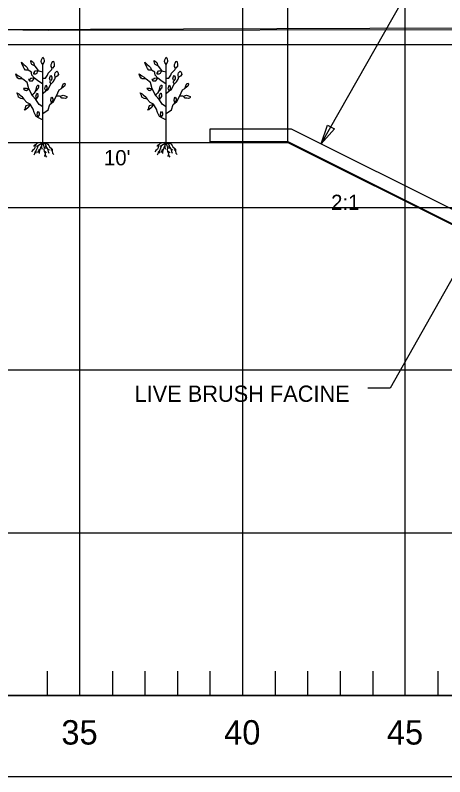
# Model space of a CAD drawing. Extents: x 1578769 to 1579225, y 724002 to 724828.
# Drawn here: x 1578858.15 to 1578871.35, y 724249.64 to 724273.06 of the extents above; entities that cross this region are included whole.
import ezdxf

# ---------------------------------------------------------------- set-up
doc = ezdxf.new("R2010")
doc.units = 0
for name, color, linetype in [('1', 7, 'Continuous'), ('Default', 7, 'Continuous'), ('Old_Level_1', 7, 'Continuous'), ('Old_Level_41', 7, 'Continuous'), ('Old_Level_42', 7, 'Continuous'), ('R_Exist Surface', 7, 'Continuous'), ('R_Fin Surface', 7, 'Continuous')]:
    doc.layers.add(name, color=color, linetype=linetype)

msp = doc.modelspace()

# ---------------------------------------------------------------- linework, layer by layer
at = {"layer": '1'}
for p, q in [((1578866.531, 724269.141), (1578866.531, 724276.038)), ((1578859, 724269.141), (1578859, 724271.541)), ((1578862.79, 724269.141), (1578862.79, 724271.541)), ((1578859.005, 724269.136), (1578859.006, 724269.14)), ((1578862.794, 724269.136), (1578862.796, 724269.14))]:
    msp.add_line(p, q, dxfattribs=at)
for points in [[(1578867.555, 724269.098), (1578873.081, 724278.846), (1578873.766, 724278.846)], [(1578859.287, 724271.427), (1578859.256, 724271.484), (1578859.256, 724271.541), (1578859.275, 724271.585), (1578859.3, 724271.636), (1578859.325, 724271.642), (1578859.35, 724271.56), (1578859.35, 724271.522), (1578859.344, 724271.49), (1578859.293, 724271.427)], [(1578863.077, 724271.427), (1578863.045, 724271.484), (1578863.045, 724271.541), (1578863.064, 724271.585), (1578863.09, 724271.636), (1578863.115, 724271.642), (1578863.14, 724271.56), (1578863.14, 724271.522), (1578863.134, 724271.49), (1578863.083, 724271.427)], [(1578858.987, 724270.947), (1578858.937, 724270.973), (1578858.836, 724271.048), (1578858.748, 724271.124), (1578858.659, 724271.213), (1578858.647, 724271.288), (1578858.647, 724271.301), (1578858.546, 724271.364)], [(1578859, 724271.301), (1578858.912, 724271.326), (1578858.861, 724271.351), (1578858.836, 724271.402), (1578858.76, 724271.49), (1578858.748, 724271.503)], [(1578859, 724271.124), (1578859.076, 724271.124), (1578859.139, 724271.213), (1578859.164, 724271.276), (1578859.278, 724271.389), (1578859.29, 724271.427)], [(1578859.379, 724271.124), (1578859.366, 724271.244), (1578859.379, 724271.288), (1578859.429, 724271.339), (1578859.461, 724271.307), (1578859.48, 724271.238), (1578859.435, 724271.187), (1578859.379, 724271.137)], [(1578862.777, 724270.947), (1578862.727, 724270.973), (1578862.626, 724271.048), (1578862.537, 724271.124), (1578862.449, 724271.213), (1578862.436, 724271.288), (1578862.436, 724271.301), (1578862.335, 724271.364)], [(1578862.79, 724271.301), (1578862.701, 724271.326), (1578862.651, 724271.351), (1578862.626, 724271.402), (1578862.55, 724271.49), (1578862.537, 724271.503)], [(1578862.79, 724271.124), (1578862.866, 724271.124), (1578862.929, 724271.213), (1578862.954, 724271.276), (1578863.068, 724271.389), (1578863.08, 724271.427)], [(1578863.168, 724271.124), (1578863.156, 724271.244), (1578863.169, 724271.288), (1578863.219, 724271.339), (1578863.251, 724271.307), (1578863.27, 724271.238), (1578863.225, 724271.187), (1578863.169, 724271.137)], [(1578858.381, 724271.086), (1578858.337, 724271.099), (1578858.262, 724271.105), (1578858.23, 724271.124), (1578858.192, 724271.181), (1578858.167, 724271.244), (1578858.167, 724271.25), (1578858.205, 724271.219), (1578858.255, 724271.194), (1578858.325, 724271.149), (1578858.381, 724271.086)], [(1578859, 724270.24), (1578858.886, 724270.316), (1578858.785, 724270.467), (1578858.684, 724270.581), (1578858.571, 724270.796), (1578858.52, 724270.985), (1578858.381, 724271.086)], [(1578859, 724270.657), (1578859.013, 724270.657), (1578859.088, 724270.733), (1578859.151, 724270.758), (1578859.24, 724270.935), (1578859.316, 724271.01), (1578859.366, 724271.086), (1578859.379, 724271.124)], [(1578859.233, 724271.036), (1578859.208, 724271.099), (1578859.221, 724271.175), (1578859.24, 724271.206), (1578859.271, 724271.156), (1578859.271, 724271.099), (1578859.233, 724271.036)], [(1578862.171, 724271.086), (1578862.127, 724271.099), (1578862.051, 724271.105), (1578862.02, 724271.124), (1578861.982, 724271.181), (1578861.957, 724271.244), (1578861.957, 724271.25), (1578861.995, 724271.219), (1578862.045, 724271.194), (1578862.115, 724271.149), (1578862.171, 724271.086)], [(1578862.79, 724270.24), (1578862.676, 724270.316), (1578862.575, 724270.467), (1578862.474, 724270.581), (1578862.361, 724270.796), (1578862.31, 724270.985), (1578862.171, 724271.086)], [(1578862.79, 724270.657), (1578862.802, 724270.657), (1578862.878, 724270.733), (1578862.941, 724270.758), (1578863.03, 724270.935), (1578863.105, 724271.01), (1578863.156, 724271.086), (1578863.168, 724271.124)], [(1578863.023, 724271.036), (1578862.998, 724271.099), (1578863.011, 724271.175), (1578863.03, 724271.206), (1578863.061, 724271.156), (1578863.061, 724271.099), (1578863.023, 724271.036)], [(1578859.088, 724270.733), (1578859.063, 724270.796), (1578859.076, 724270.871), (1578859.095, 724270.903), (1578859.126, 724270.853), (1578859.126, 724270.796), (1578859.088, 724270.733)], [(1578859.24, 724270.935), (1578859.233, 724270.973), (1578859.215, 724270.998), (1578859.233, 724271.036)], [(1578859.568, 724270.808), (1578859.6, 724270.89), (1578859.631, 724270.954), (1578859.675, 724270.966), (1578859.682, 724270.935), (1578859.663, 724270.878), (1578859.625, 724270.84), (1578859.568, 724270.808)], [(1578862.878, 724270.733), (1578862.853, 724270.796), (1578862.866, 724270.871), (1578862.884, 724270.903), (1578862.916, 724270.853), (1578862.916, 724270.796), (1578862.878, 724270.733)], [(1578863.03, 724270.935), (1578863.023, 724270.973), (1578863.004, 724270.998), (1578863.023, 724271.036)], [(1578863.358, 724270.808), (1578863.389, 724270.89), (1578863.421, 724270.954), (1578863.465, 724270.966), (1578863.471, 724270.935), (1578863.453, 724270.878), (1578863.415, 724270.84), (1578863.358, 724270.808)], [(1578858.571, 724270.796), (1578858.497, 724270.802), (1578858.439, 724270.802), (1578858.401, 724270.802), (1578858.42, 724270.783), (1578858.458, 724270.754), (1578858.497, 724270.744), (1578858.573, 724270.792)], [(1578858.684, 724270.581), (1578858.703, 724270.644), (1578858.754, 724270.682), (1578858.785, 724270.733)], [(1578859, 724270.032), (1578859.164, 724270.151), (1578859.215, 724270.316), (1578859.328, 724270.404), (1578859.416, 724270.581), (1578859.505, 724270.758), (1578859.568, 724270.808)], [(1578862.361, 724270.796), (1578862.286, 724270.802), (1578862.229, 724270.802), (1578862.191, 724270.802), (1578862.21, 724270.783), (1578862.248, 724270.754), (1578862.286, 724270.744), (1578862.363, 724270.792)], [(1578862.474, 724270.581), (1578862.493, 724270.644), (1578862.544, 724270.682), (1578862.575, 724270.733)], [(1578862.79, 724270.032), (1578862.954, 724270.151), (1578863.004, 724270.316), (1578863.118, 724270.404), (1578863.206, 724270.581), (1578863.295, 724270.758), (1578863.358, 724270.808)], [(1578859.003, 724269.837), (1578858.964, 724269.846), (1578858.888, 724269.894), (1578858.793, 724269.942), (1578858.735, 724270.066), (1578858.697, 724270.171), (1578858.611, 724270.324), (1578858.506, 724270.372), (1578858.411, 724270.477), (1578858.411, 724270.477)], [(1578859.269, 724270.367), (1578859.244, 724270.43), (1578859.257, 724270.506), (1578859.276, 724270.537), (1578859.307, 724270.487), (1578859.307, 724270.43), (1578859.269, 724270.367)], [(1578859.416, 724270.581), (1578859.48, 724270.581), (1578859.505, 724270.581), (1578859.536, 724270.568)], [(1578859.536, 724270.568), (1578859.625, 724270.6), (1578859.688, 724270.575), (1578859.732, 724270.556), (1578859.732, 724270.524), (1578859.713, 724270.505), (1578859.682, 724270.499), (1578859.637, 724270.505), (1578859.587, 724270.505), (1578859.536, 724270.568)], [(1578862.792, 724269.837), (1578862.754, 724269.846), (1578862.678, 724269.894), (1578862.582, 724269.942), (1578862.525, 724270.066), (1578862.487, 724270.171), (1578862.401, 724270.324), (1578862.296, 724270.372), (1578862.201, 724270.477), (1578862.201, 724270.477)], [(1578863.059, 724270.367), (1578863.034, 724270.43), (1578863.047, 724270.506), (1578863.065, 724270.537), (1578863.097, 724270.487), (1578863.097, 724270.43), (1578863.059, 724270.367)], [(1578863.206, 724270.581), (1578863.269, 724270.581), (1578863.295, 724270.581), (1578863.326, 724270.568)], [(1578863.326, 724270.568), (1578863.415, 724270.6), (1578863.478, 724270.575), (1578863.522, 724270.556), (1578863.522, 724270.524), (1578863.503, 724270.505), (1578863.471, 724270.499), (1578863.427, 724270.505), (1578863.377, 724270.505), (1578863.326, 724270.568)], [(1578858.849, 724269.927), (1578858.824, 724269.991), (1578858.837, 724270.066), (1578858.856, 724270.098), (1578858.887, 724270.047), (1578858.887, 724269.991), (1578858.849, 724269.927)], [(1578862.639, 724269.927), (1578862.614, 724269.991), (1578862.626, 724270.066), (1578862.645, 724270.098), (1578862.677, 724270.047), (1578862.677, 724269.991), (1578862.639, 724269.927)], [(1578859, 724269.141), (1578858.949, 724269.135), (1578858.933, 724269.139), (1578858.875, 724269.131), (1578858.84, 724269.124), (1578858.813, 724269.108), (1578858.782, 724269.077), (1578858.758, 724269.042), (1578858.751, 724269.007), (1578858.751, 724268.976), (1578858.735, 724268.941), (1578858.724, 724268.926), (1578858.685, 724268.898), (1578858.65, 724268.852)], [(1578858.782, 724269.077), (1578858.739, 724269.058), (1578858.724, 724269.034), (1578858.712, 724269.026)], [(1578859, 724269.141), (1578858.933, 724269.092), (1578858.894, 724269.073), (1578858.855, 724269.042), (1578858.836, 724269.003), (1578858.828, 724268.972), (1578858.789, 724268.887), (1578858.755, 724268.844), (1578858.743, 724268.794), (1578858.727, 724268.751)], [(1578858.855, 724269.042), (1578858.813, 724269.034), (1578858.809, 724269.019)], [(1578859, 724269.141), (1578858.96, 724269.046), (1578858.925, 724268.992), (1578858.914, 724268.941), (1578858.898, 724268.902), (1578858.887, 724268.844), (1578858.887, 724268.805)], [(1578858.96, 724269.046), (1578858.96, 724268.992), (1578858.964, 724268.968), (1578858.976, 724268.937)], [(1578859, 724269.141), (1578859.084, 724269.125), (1578859.127, 724269.112), (1578859.154, 724269.092), (1578859.181, 724269.054), (1578859.201, 724269.007), (1578859.267, 724268.96), (1578859.29, 724268.933), (1578859.29, 724268.875), (1578859.294, 724268.817), (1578859.333, 724268.778)], [(1578859, 724269.141), (1578859.069, 724269.104), (1578859.092, 724269.05), (1578859.104, 724268.995), (1578859.139, 724268.949), (1578859.162, 724268.863), (1578859.185, 724268.813)], [(1578859, 724269.141), (1578859.007, 724269.077), (1578859.018, 724269.05), (1578859.03, 724269.011), (1578859.038, 724268.995), (1578859.038, 724268.964), (1578859.026, 724268.926), (1578859.038, 724268.879), (1578859.053, 724268.844), (1578859.073, 724268.805), (1578859.073, 724268.77), (1578859.084, 724268.728), (1578859.108, 724268.693)], [(1578859.092, 724269.05), (1578859.08, 724269.019), (1578859.069, 724269.003), (1578859.088, 724268.957)], [(1578862.79, 724269.141), (1578862.738, 724269.135), (1578862.723, 724269.139), (1578862.665, 724269.131), (1578862.63, 724269.124), (1578862.603, 724269.108), (1578862.572, 724269.077), (1578862.548, 724269.042), (1578862.541, 724269.007), (1578862.541, 724268.976), (1578862.525, 724268.941), (1578862.513, 724268.926), (1578862.475, 724268.898), (1578862.44, 724268.852)], [(1578862.572, 724269.077), (1578862.529, 724269.058), (1578862.513, 724269.034), (1578862.502, 724269.026)], [(1578862.79, 724269.141), (1578862.723, 724269.092), (1578862.684, 724269.073), (1578862.645, 724269.042), (1578862.626, 724269.003), (1578862.618, 724268.972), (1578862.579, 724268.887), (1578862.544, 724268.844), (1578862.533, 724268.794), (1578862.517, 724268.751)], [(1578862.645, 724269.042), (1578862.603, 724269.034), (1578862.599, 724269.019)], [(1578862.79, 724269.141), (1578862.75, 724269.046), (1578862.715, 724268.992), (1578862.703, 724268.941), (1578862.688, 724268.902), (1578862.676, 724268.844), (1578862.676, 724268.805)], [(1578862.75, 724269.046), (1578862.75, 724268.992), (1578862.754, 724268.968), (1578862.766, 724268.937)], [(1578862.79, 724269.141), (1578862.874, 724269.125), (1578862.917, 724269.112), (1578862.944, 724269.092), (1578862.971, 724269.054), (1578862.991, 724269.007), (1578863.057, 724268.96), (1578863.08, 724268.933), (1578863.08, 724268.875), (1578863.084, 724268.817), (1578863.122, 724268.778)], [(1578862.79, 724269.141), (1578862.859, 724269.104), (1578862.882, 724269.05), (1578862.894, 724268.995), (1578862.928, 724268.949), (1578862.952, 724268.863), (1578862.975, 724268.813)], [(1578862.79, 724269.141), (1578862.797, 724269.077), (1578862.808, 724269.05), (1578862.82, 724269.011), (1578862.828, 724268.995), (1578862.828, 724268.964), (1578862.816, 724268.926), (1578862.828, 724268.879), (1578862.843, 724268.844), (1578862.863, 724268.805), (1578862.863, 724268.77), (1578862.874, 724268.728), (1578862.897, 724268.693)], [(1578862.882, 724269.05), (1578862.87, 724269.019), (1578862.859, 724269.003), (1578862.878, 724268.957)], [(1578858.789, 724268.887), (1578858.782, 724268.832), (1578858.786, 724268.817)], [(1578858.914, 724268.941), (1578858.867, 724268.902), (1578858.863, 724268.883), (1578858.855, 724268.879), (1578858.836, 724268.821)], [(1578859.038, 724268.879), (1578859.073, 724268.863), (1578859.096, 724268.844), (1578859.1, 724268.828)], [(1578859.073, 724268.77), (1578859.046, 724268.735), (1578859.049, 724268.712)], [(1578859.139, 724268.949), (1578859.174, 724268.929), (1578859.193, 724268.918), (1578859.205, 724268.906)], [(1578859.267, 724268.96), (1578859.255, 724268.922), (1578859.251, 724268.902)], [(1578862.579, 724268.887), (1578862.572, 724268.832), (1578862.575, 724268.817)], [(1578862.703, 724268.941), (1578862.657, 724268.902), (1578862.653, 724268.883), (1578862.645, 724268.879), (1578862.626, 724268.821)], [(1578862.828, 724268.879), (1578862.863, 724268.863), (1578862.886, 724268.844), (1578862.89, 724268.828)], [(1578862.863, 724268.77), (1578862.835, 724268.735), (1578862.839, 724268.712)], [(1578862.928, 724268.949), (1578862.963, 724268.929), (1578862.983, 724268.918), (1578862.994, 724268.906)], [(1578863.057, 724268.96), (1578863.045, 724268.922), (1578863.041, 724268.902)], [(1578871.885, 724265.503), (1578869.669, 724261.594), (1578868.984, 724261.594)]]:
    msp.add_lwpolyline(points, dxfattribs=at)
for points in [[(1578858.546, 724271.364), (1578858.47, 724271.37), (1578858.426, 724271.415), (1578858.4, 724271.459), (1578858.356, 724271.573), (1578858.344, 724271.61), (1578858.419, 724271.541), (1578858.464, 724271.497), (1578858.514, 724271.446)], [(1578858.748, 724271.503), (1578858.666, 724271.541), (1578858.64, 724271.579), (1578858.628, 724271.642), (1578858.628, 724271.667), (1578858.666, 724271.648), (1578858.71, 724271.598)], [(1578859, 724271.541), (1578858.956, 724271.604), (1578858.943, 724271.629), (1578858.956, 724271.68), (1578858.968, 724271.705), (1578858.994, 724271.762), (1578859.013, 724271.756), (1578859.032, 724271.705), (1578859.038, 724271.667), (1578859.044, 724271.629)], [(1578862.335, 724271.364), (1578862.26, 724271.37), (1578862.216, 724271.415), (1578862.19, 724271.459), (1578862.146, 724271.573), (1578862.134, 724271.61), (1578862.209, 724271.541), (1578862.253, 724271.497), (1578862.304, 724271.446)], [(1578862.537, 724271.503), (1578862.455, 724271.541), (1578862.43, 724271.579), (1578862.417, 724271.642), (1578862.417, 724271.667), (1578862.455, 724271.648), (1578862.5, 724271.598)], [(1578862.79, 724271.541), (1578862.746, 724271.604), (1578862.733, 724271.629), (1578862.746, 724271.68), (1578862.758, 724271.705), (1578862.784, 724271.762), (1578862.802, 724271.756), (1578862.821, 724271.705), (1578862.828, 724271.667), (1578862.834, 724271.629)], [(1578858.861, 724271.351), (1578858.793, 724271.337), (1578858.764, 724271.337), (1578858.735, 724271.327), (1578858.735, 724271.289), (1578858.707, 724271.26), (1578858.726, 724271.251), (1578858.783, 724271.251), (1578858.821, 724271.27), (1578858.84, 724271.318)], [(1578862.651, 724271.351), (1578862.582, 724271.337), (1578862.554, 724271.337), (1578862.525, 724271.327), (1578862.525, 724271.289), (1578862.496, 724271.26), (1578862.516, 724271.251), (1578862.573, 724271.251), (1578862.611, 724271.27), (1578862.63, 724271.318)], [(1578858.748, 724271.124), (1578858.707, 724271.117), (1578858.649, 724271.108), (1578858.621, 724271.108), (1578858.611, 724271.079), (1578858.563, 724271.079), (1578858.592, 724271.041), (1578858.63, 724271.041), (1578858.678, 724271.041), (1578858.716, 724271.079)], [(1578862.537, 724271.124), (1578862.496, 724271.117), (1578862.439, 724271.108), (1578862.411, 724271.108), (1578862.401, 724271.079), (1578862.353, 724271.079), (1578862.382, 724271.041), (1578862.42, 724271.041), (1578862.468, 724271.041), (1578862.506, 724271.079)], [(1578858.785, 724270.733), (1578858.804, 724270.827), (1578858.817, 724270.865), (1578858.823, 724270.884), (1578858.849, 724270.909), (1578858.867, 724270.909), (1578858.867, 724270.84), (1578858.855, 724270.815)], [(1578862.575, 724270.733), (1578862.594, 724270.827), (1578862.607, 724270.865), (1578862.613, 724270.884), (1578862.638, 724270.909), (1578862.657, 724270.909), (1578862.657, 724270.84), (1578862.645, 724270.815)], [(1578858.411, 724270.477), (1578858.325, 724270.496), (1578858.248, 724270.534), (1578858.239, 724270.592), (1578858.201, 724270.668), (1578858.258, 724270.639), (1578858.296, 724270.611), (1578858.353, 724270.553), (1578858.382, 724270.515)], [(1578858.785, 724270.467), (1578858.793, 724270.544), (1578858.783, 724270.563), (1578858.802, 724270.62), (1578858.831, 724270.659), (1578858.84, 724270.659), (1578858.85, 724270.601), (1578858.85, 724270.553)], [(1578862.201, 724270.477), (1578862.115, 724270.496), (1578862.038, 724270.534), (1578862.029, 724270.592), (1578861.991, 724270.668), (1578862.048, 724270.639), (1578862.086, 724270.611), (1578862.143, 724270.553), (1578862.172, 724270.515)], [(1578862.575, 724270.467), (1578862.582, 724270.544), (1578862.573, 724270.563), (1578862.592, 724270.62), (1578862.621, 724270.659), (1578862.63, 724270.659), (1578862.64, 724270.601), (1578862.64, 724270.553)], [(1578858.611, 724270.324), (1578858.554, 724270.286), (1578858.478, 724270.267), (1578858.458, 724270.21), (1578858.458, 724270.171), (1578858.43, 724270.152), (1578858.468, 724270.162), (1578858.544, 724270.229), (1578858.554, 724270.229), (1578858.611, 724270.295)], [(1578862.401, 724270.324), (1578862.344, 724270.286), (1578862.267, 724270.267), (1578862.248, 724270.21), (1578862.248, 724270.171), (1578862.22, 724270.152), (1578862.258, 724270.162), (1578862.334, 724270.229), (1578862.344, 724270.229), (1578862.401, 724270.295)], [(1578867.956, 724269.561), (1578867.555, 724269.098), (1578867.747, 724269.68)]]:
    msp.add_lwpolyline(points, close=True, dxfattribs=at)
at = {"layer": 'Default'}
msp.add_line((1578825.136, 724252.141), (1579225.136, 724252.141), dxfattribs=at)
msp.add_lwpolyline([(1578826.025, 724272.503), (1578843.356, 724272.54), (1578848.216, 724272.563), (1578852.656, 724272.595), (1578873.806, 724272.679), (1578875.706, 724271.556), (1578889.515, 724263.067), (1578894.196, 724261.454), (1578913.456, 724256.023), (1578914.486, 724256.05), (1578915.035, 724256.065), (1578992.496, 724256.633), (1578992.515, 724256.633), (1578992.566, 724256.634), (1578992.736, 724256.639), (1578993.706, 724256.668), (1579090.356, 724259.528), (1579113.086, 724262.229), (1579131.176, 724264.398), (1579155.015, 724266.722), (1579177.006, 724269.229), (1579191.525, 724270.885)], dxfattribs=at)
at = {"layer": 'Old_Level_1'}
for points in [[(1578820.135, 724284.641), (1578927.635, 724284.641), (1578927.635, 724249.641), (1578820.135, 724249.641)], [(1578825.135, 724282.141), (1578925.135, 724282.141), (1578925.135, 724252.141), (1578825.135, 724252.141)]]:
    msp.add_lwpolyline(points, close=True, dxfattribs=at)
at = {"layer": 'Old_Level_41'}
for p, q in [((1578860.135, 724252.141), (1578860.135, 724282.141)), ((1578865.135, 724282.141), (1578865.135, 724252.141)), ((1578870.135, 724252.141), (1578870.135, 724282.141))]:
    msp.add_line(p, q, dxfattribs=at)
for points in [[(1578925.135, 724272.141), (1578825.135, 724272.141)], [(1578825.135, 724267.141), (1578925.135, 724267.141)], [(1578925.135, 724262.141), (1578825.135, 724262.141)], [(1578825.135, 724257.141), (1578925.135, 724257.141)]]:
    msp.add_lwpolyline(points, dxfattribs=at)
at = {"layer": 'Old_Level_42'}
for p, q in [((1578859.135, 724252.891), (1578859.135, 724252.141)), ((1578861.135, 724252.891), (1578861.135, 724252.141)), ((1578862.135, 724252.891), (1578862.135, 724252.141)), ((1578863.135, 724252.891), (1578863.135, 724252.141)), ((1578864.135, 724252.891), (1578864.135, 724252.141)), ((1578866.135, 724252.891), (1578866.135, 724252.141)), ((1578867.135, 724252.891), (1578867.135, 724252.141)), ((1578868.135, 724252.891), (1578868.135, 724252.141)), ((1578869.135, 724252.891), (1578869.135, 724252.141)), ((1578871.135, 724252.891), (1578871.135, 724252.141))]:
    msp.add_line(p, q, dxfattribs=at)
at = {"layer": 'R_Exist Surface'}
msp.add_lwpolyline([(1578826.062, 724272.509), (1578843.255, 724272.529), (1578855.204, 724272.649), (1578859.177, 724272.597), (1578872.167, 724272.617), (1578873.087, 724272.657), (1578874.163, 724272.457), (1578875.161, 724271.898), (1578886.138, 724265.225), (1578890.363, 724262.7), (1578891.18, 724262.468), (1578894.233, 724261.427), (1578900.147, 724259.744), (1578907.197, 724257.773), (1578912.15, 724256.411), (1578913.135, 724256.113), (1578914.178, 724256.033), (1578918.136, 724256.056), (1578925.136, 724256.105)], dxfattribs=at)
at = {"layer": 'R_Fin Surface'}
for p, q in [((1578864.141, 724269.161), (1578864.141, 724269.561)), ((1578864.141, 724269.561), (1578866.63, 724269.561)), ((1578866.63, 724269.561), (1578872.681, 724266.536)), ((1578856.531, 724269.141), (1578866.531, 724269.141)), ((1578856.531, 724269.141), (1578866.531, 724269.141)), ((1578866.536, 724269.161), (1578864.141, 724269.161)), ((1578866.531, 724269.141), (1578872.582, 724266.116)), ((1578866.531, 724269.141), (1578872.582, 724266.116)), ((1578872.586, 724266.136), (1578866.536, 724269.161))]:
    msp.add_line(p, q, dxfattribs=at)

# ---------------------------------------------------------------- texts
at = {"layer": '1'}
for s, height, p in [("10'", 0.4687, (1578860.876, 724268.441)), ('2:1', 0.4687, (1578867.856, 724267.069)), ('LIVE BRUSH FACINE', 0.5, (1578861.816, 724261.169)), ('35', 0.75, (1578859.569, 724250.631)), ('40', 0.75, (1578864.569, 724250.631)), ('45', 0.75, (1578869.569, 724250.631))]:
    msp.add_text(s, height=height, dxfattribs=at).set_placement(p)

doc.saveas('drawing.dxf')
